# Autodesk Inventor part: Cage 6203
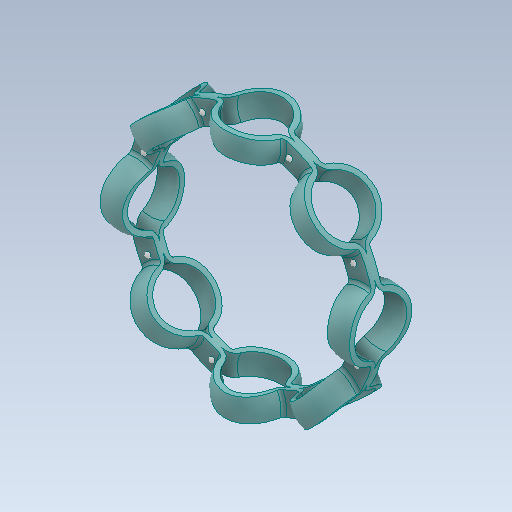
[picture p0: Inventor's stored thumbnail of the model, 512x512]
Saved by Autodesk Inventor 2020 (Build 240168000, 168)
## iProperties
Created: 2001-06
Part Number: Cage 6203
Material: Générique
Document SubType Name: Modeling
Designer: Bruno
Density: 1 g/cm^3
Appearance: Par défaut
Author: Bruno
Sending System: SolidWorks 2011
Last Author: frederic
Last Saved: 2012-02-20
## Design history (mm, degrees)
feature "Bossage-Symétrie1"
node "Solide1"
